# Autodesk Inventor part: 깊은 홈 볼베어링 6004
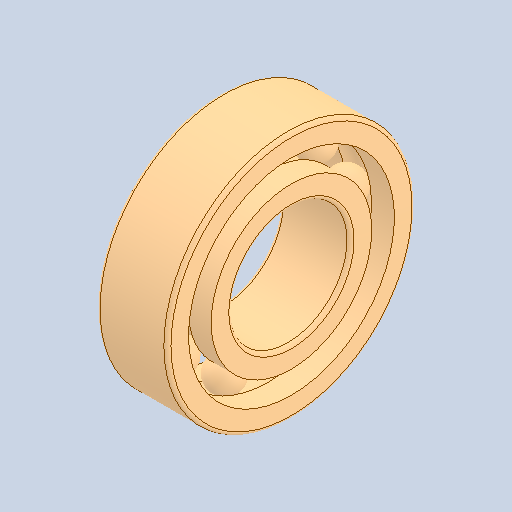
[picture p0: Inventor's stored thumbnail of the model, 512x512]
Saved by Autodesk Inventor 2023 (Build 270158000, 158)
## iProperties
Created: 2024-09
Part Number: 깊은 홈 볼베어링 6004
Material: 강철, 연강
Description: 깊은 그루브 볼 베어링
Document SubType Name: Modeling
Designer: home
Density: 7.85 g/cm^3
Appearance: 기본값
Author: jhkim
Sending System: Autodesk Inventor 2025
Preprocessor: ST-DEVELOPER v20
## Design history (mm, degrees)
feature "Solid1"
feature "Solid1:1"
feature "Solid1:2"
feature "Solid1:3"
feature "Solid1:4"
feature "Solid1:5"
feature "Solid1:6"
feature "Solid1:7"
feature "Solid1:8"
feature "Solid1:9"
feature "Solid1:10"
node "솔리드1"
node "솔리드2"
node "솔리드3"
node "솔리드4"
node "솔리드5"
node "솔리드6"
node "솔리드7"
node "솔리드8"
node "솔리드9"
node "솔리드10"
node "솔리드11"
